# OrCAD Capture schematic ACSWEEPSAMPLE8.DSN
size A
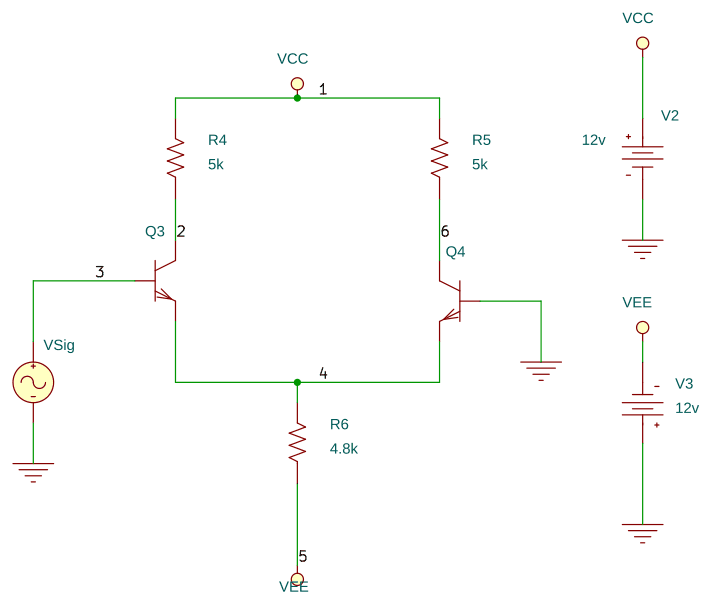
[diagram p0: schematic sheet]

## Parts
Q3  QbreakN
Q4  QbreakN
R4  5k  [AX/RC05]
R5  5k  [AX/RC05]
R6  4.8k  [AX/RC05]
V2  VDC
V3  VDC
VSig  VAC

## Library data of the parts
Q3 Q4 = QbreakN: BF: 60
R4-R6 = R
V2 V3 = VDC: DC: 12v
VSig = VAC

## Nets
VCC: R4.2 R5.2 V2.0(+)
VEE: R6.1 V3.1(-)
0: Q4.0(b) V2.1(-) V3.0(+) VSig.2(-)
2: Q3.1(c) R4.1
3: Q3.0(b) VSig.1(+)
4: Q3.2(e) Q4.2(e) R6.2
6: Q4.1(c) R5.1
